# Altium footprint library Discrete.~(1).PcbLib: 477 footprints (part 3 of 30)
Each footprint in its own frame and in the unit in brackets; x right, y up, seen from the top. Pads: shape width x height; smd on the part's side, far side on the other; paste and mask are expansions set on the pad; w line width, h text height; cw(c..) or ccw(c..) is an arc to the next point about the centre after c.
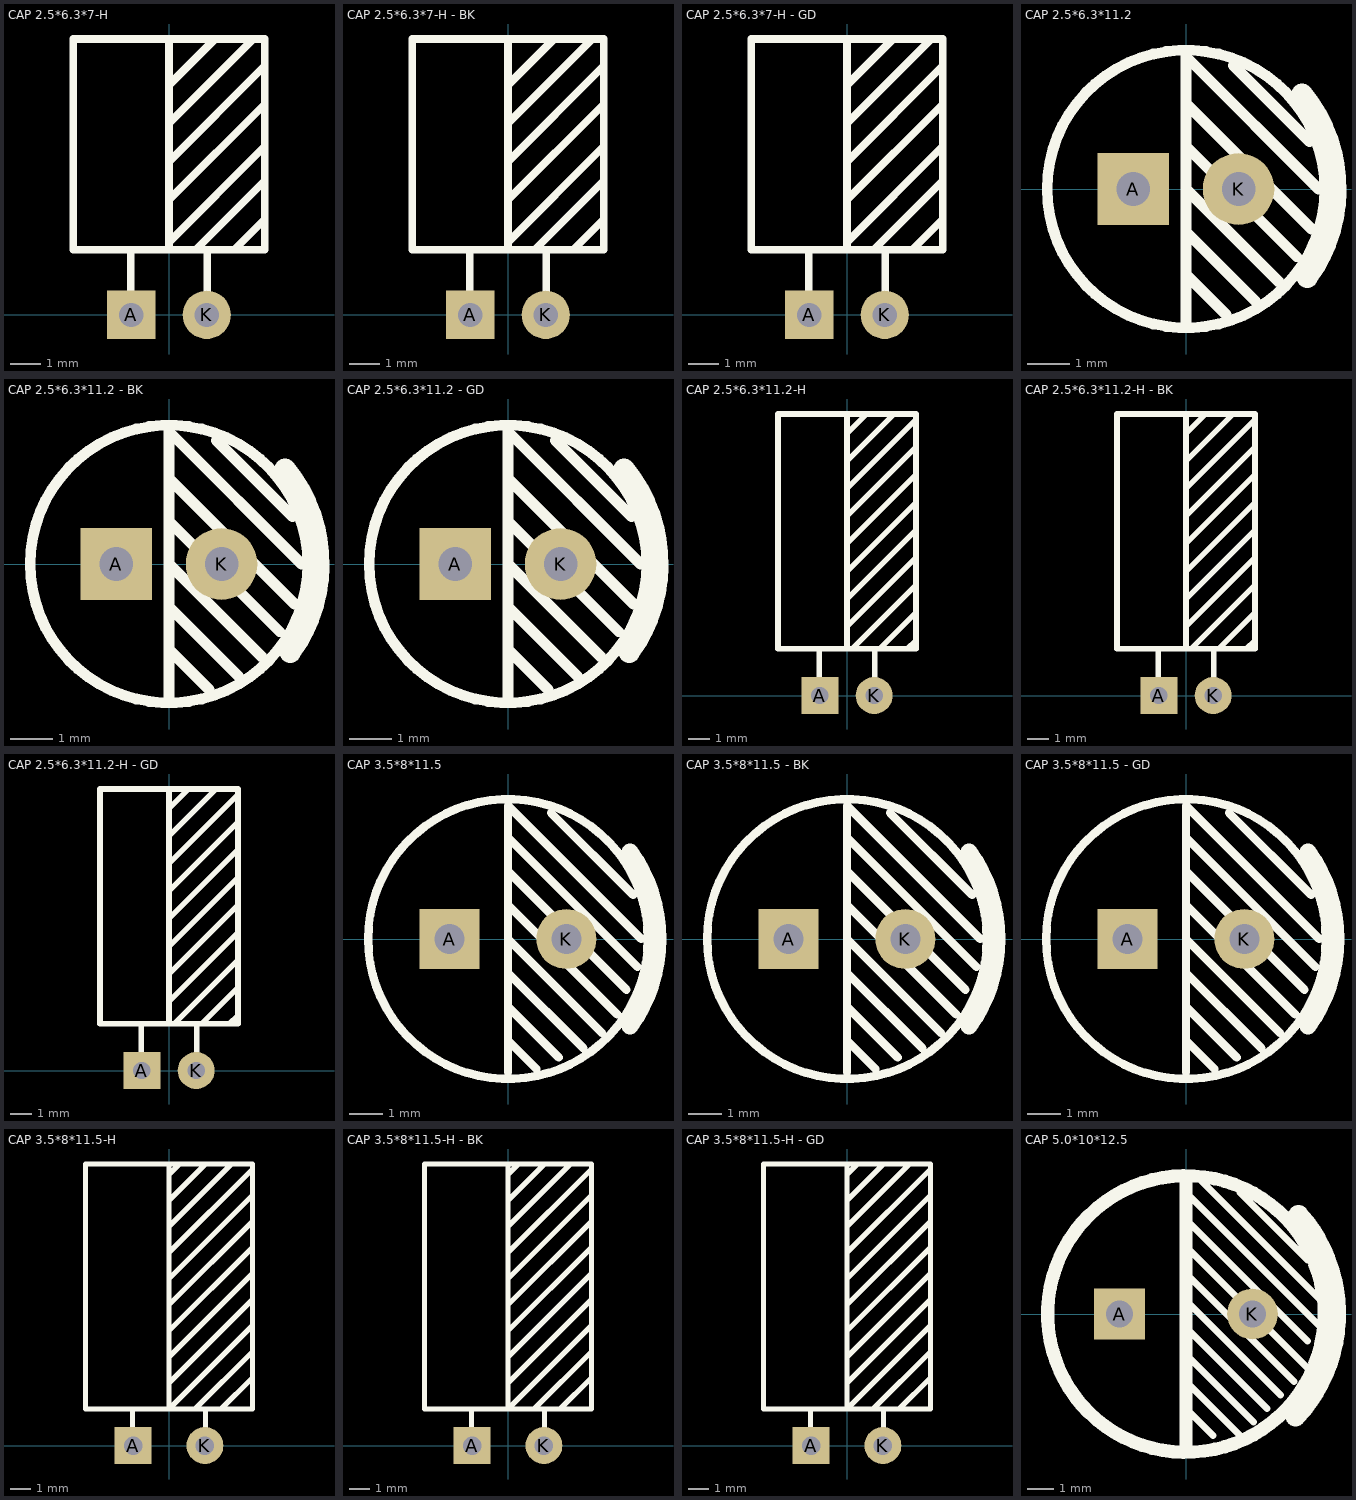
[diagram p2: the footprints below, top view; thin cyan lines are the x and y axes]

## CAP 2.5*6.3*7-H [mm] "脚距2.5mm直径6.3mm高度7mm"
pads (2):
  rect 1.6x1.6 hole 0.8: A(-1.25,0)
  round 1.6 hole 0.8: K(1.25,0)
Top Overlay:
  lines w0.254: -1.27,0.762 -1.27,2.159 ; 0,2.159 0,9.144 ; 0,2.413 3.175,5.588 3.175,5.715 ; 0,3.81 3.175,6.985 ; 0,5.08 3.175,8.255 ; 0,6.35 2.794,9.144 ; 0,7.62 1.524,9.144 ; 0.889,2.159 3.175,4.445 ; 1.27,0.762 1.27,2.159 ; 2.159,2.159 3.175,3.175 ; -3.175,2.159 3.175,2.159 3.175,9.144 -3.175,9.144 -3.175,2.159
3D body "CAP 2.5X6.3X7-H.STEP": height 6.32, standoff -3.48, extent -3.15,-0.3 3.16,8.91

## CAP 2.5*6.3*7-H - BK [mm] "脚距2.5mm直径6.3mm高度7mm"
pads (2):
  rect 1.6x1.6 hole 0.8: A(-1.25,0)
  round 1.6 hole 0.8: K(1.25,0)
Top Overlay:
  lines w0.254: -1.27,0.762 -1.27,2.159 ; 0,2.159 0,9.144 ; 0,2.413 3.175,5.588 3.175,5.715 ; 0,3.81 3.175,6.985 ; 0,5.08 3.175,8.255 ; 0,6.35 2.794,9.144 ; 0,7.62 1.524,9.144 ; 0.889,2.159 3.175,4.445 ; 1.27,0.762 1.27,2.159 ; 2.159,2.159 3.175,3.175 ; -3.175,2.159 3.175,2.159 3.175,9.144 -3.175,9.144 -3.175,2.159
3D body "CAP 2.5X6.3X7-H.STEP": height 6.32, standoff -3.48, extent -3.15,-0.3 3.16,8.91

## CAP 2.5*6.3*7-H - GD [mm] "脚距2.5mm直径6.3mm高度7mm"
pads (2):
  rect 1.6x1.6 hole 0.8: A(-1.25,0)
  round 1.6 hole 0.8: K(1.25,0)
Top Overlay:
  lines w0.254: -1.27,0.762 -1.27,2.159 ; 0,2.159 0,9.144 ; 0,2.413 3.175,5.588 3.175,5.715 ; 0,3.81 3.175,6.985 ; 0,5.08 3.175,8.255 ; 0,6.35 2.794,9.144 ; 0,7.62 1.524,9.144 ; 0.889,2.159 3.175,4.445 ; 1.27,0.762 1.27,2.159 ; 2.159,2.159 3.175,3.175 ; -3.175,2.159 -3.175,9.144 3.175,9.144 3.175,2.159 -3.175,2.159
3D body "CAP 2.5X6.3X7-H.STEP": height 6.32, standoff -3.48, extent -3.15,-0.3 3.16,8.91

## CAP 2.5*6.3*11.2 [mm] "脚距2.5mm直径6.3mm高度11.2mm"
pads (2):
  rect 1.7x1.7 hole 0.8: A(-1.25,0)
  round 1.7 hole 0.8: K(1.25,0)
Top Overlay:
  circle w0.254: c0,0 r3.3
  lines w0.254: 0,-3.15 0,3.15 ; 0,-2.032 0.953,-2.984 ; 0,-1.016 1.638,-2.654 ; 0,0 2.21,-2.21 ; 0,1.016 2.629,-1.613 ; 0,2.032 2.984,-0.953 ; 0,3.048 0.102,3.048 3.15,0 ; 1.13,2.934 2.934,1.13
  lines w0.504: 2.759,2.258 cw(c0,0) 2.883,-2.097
3D body "CAP 2.5X6.3X11.2.STEP": height 11.23, standoff -3.38, extent -3.15,-3.15 3.16,3.15

## CAP 2.5*6.3*11.2 - BK [mm] "脚距2.5mm直径6.3mm高度11.2mm"
pads (2):
  rect 1.7x1.7 hole 0.8: A(-1.25,0)
  round 1.7 hole 0.8: K(1.25,0)
Top Overlay:
  circle w0.254: c0,0 r3.3
  lines w0.254: 0,-3.15 0,3.15 ; 0,-2.032 0.953,-2.984 ; 0,-1.016 1.638,-2.654 ; 0,0 2.21,-2.21 ; 0,1.016 2.629,-1.613 ; 0,2.032 2.984,-0.953 ; 0,3.048 0.102,3.048 3.15,0 ; 1.13,2.934 2.934,1.13
  lines w0.504: 2.759,2.258 cw(c0,0) 2.883,-2.097
3D body "CAP 2.5X6.3X11.2.STEP": height 11.24, standoff -3.37, extent -3.15,-3.15 3.16,3.15

## CAP 2.5*6.3*11.2 - GD [mm] "脚距2.5mm直径6.3mm高度11.2mm"
pads (2):
  rect 1.7x1.7 hole 0.8: A(-1.25,0)
  round 1.7 hole 0.8: K(1.25,0)
Top Overlay:
  circle w0.254: c0,0 r3.3
  lines w0.254: 0,-3.15 0,3.15 ; 0,-2.032 0.953,-2.984 ; 0,-1.016 1.638,-2.654 ; 0,0 2.21,-2.21 ; 0,1.016 2.629,-1.613 ; 0,2.032 2.984,-0.953 ; 0,3.048 0.102,3.048 3.15,0 ; 1.13,2.934 2.934,1.13
  lines w0.504: 2.759,2.258 cw(c0,0) 2.883,-2.097
3D body "CAP 2.5X6.3X11.2.STEP": height 11.24, standoff -3.37, extent -3.15,-3.15 3.16,3.15

## CAP 2.5*6.3*11.2-H [mm] "脚距2.5mm直径6.3mm高度11.2mm"
pads (2):
  rect 1.7x1.7 hole 0.8: A(-1.25,0)
  round 1.7 hole 0.8: K(1.25,0)
Top Overlay:
  lines w0.254: -1.27,0.635 -1.27,2.032 ; 0,2.159 0,12.954 ; 0,3.175 3.175,6.35 ; 0,4.445 3.175,7.62 ; 0,5.715 3.175,8.89 ; 0,6.985 3.175,10.16 ; 0,8.255 3.175,11.43 ; 0,9.525 3.175,12.7 ; 0,10.795 2.159,12.954 ; 0,12.065 0.889,12.954 ; 0.254,2.159 3.175,5.08 3.175,4.953 ; 1.27,0.635 1.27,2.159 ; 1.524,2.159 3.175,3.81 ; 2.794,2.159 3.175,2.54 ; -3.175,2.159 3.175,2.159 3.175,12.954 -3.175,12.954 -3.175,2.159
3D body "CAP 2.5X6.3X11.2-H.STEP": height 6.32, standoff -3.48, extent -3.15,-0.3 3.16,13.11

## CAP 2.5*6.3*11.2-H - BK [mm] "脚距2.5mm直径6.3mm高度11.2mm"
pads (2):
  rect 1.7x1.7 hole 0.8: A(-1.25,0)
  round 1.7 hole 0.8: K(1.25,0)
Top Overlay:
  lines w0.254: -1.27,0.635 -1.27,2.032 ; 0,2.159 0,12.954 ; 0,3.175 3.175,6.35 ; 0,4.445 3.175,7.62 ; 0,5.715 3.175,8.89 ; 0,6.985 3.175,10.16 ; 0,8.255 3.175,11.43 ; 0,9.525 3.175,12.7 ; 0,10.795 2.159,12.954 ; 0,12.065 0.889,12.954 ; 0.254,2.159 3.175,5.08 3.175,4.953 ; 1.27,0.635 1.27,2.159 ; 1.524,2.159 3.175,3.81 ; 2.794,2.159 3.175,2.54 ; -3.175,2.159 3.175,2.159 3.175,12.954 -3.175,12.954 -3.175,2.159
3D body "CAP 2.5X6.3X11.2-H.STEP": height 6.32, standoff -3.48, extent -3.15,-0.3 3.16,13.11

## CAP 2.5*6.3*11.2-H - GD [mm] "脚距2.5mm直径6.3mm高度11.2mm"
pads (2):
  rect 1.7x1.7 hole 0.8: A(-1.25,0)
  round 1.7 hole 0.8: K(1.25,0)
Top Overlay:
  lines w0.254: -1.27,0.635 -1.27,2.032 ; 0,2.159 0,12.954 ; 0,3.175 3.175,6.35 ; 0,4.445 3.175,7.62 ; 0,5.715 3.175,8.89 ; 0,6.985 3.175,10.16 ; 0,8.255 3.175,11.43 ; 0,9.525 3.175,12.7 ; 0,10.795 2.159,12.954 ; 0,12.065 0.889,12.954 ; 0.254,2.159 3.175,5.08 3.175,4.953 ; 1.27,0.635 1.27,2.159 ; 1.524,2.159 3.175,3.81 ; 2.794,2.159 3.175,2.54 ; -3.175,2.159 -3.175,12.954 3.175,12.954 3.175,2.159 -3.175,2.159
3D body "CAP 2.5X6.3X11.2-H.STEP": height 6.32, standoff -3.48, extent -3.15,-0.3 3.16,13.11

## CAP 3.5*8*11.5 [mm] "脚距3.5mm直径8mm高度11.5mm"
pads (2):
  rect 1.8x1.8 hole 0.9: A(-1.75,0)
  round 1.8 hole 0.9: K(1.75,0)
Top Overlay:
  circle w0.254: c0,0 r4.2
  lines w0.254: 0,-4 0,4 4,0 ; 0,-3.048 0.851,-3.899 ; 0,-2.032 1.524,-3.556 ; 0,-1.016 2.261,-3.277 ; 0,0 2.807,-2.807 ; 0,1.016 3.277,-2.261 ; 0,2.032 3.556,-1.524 ; 0,3.048 3.886,-0.838 ; 1.295,3.785 3.759,1.321
  lines w0.504: 3.663,-2.616 ccw(c0,0) 3.663,2.616
3D body "CAP 3.5X8X11.5.STEP": height 11.53, standoff -3.38, extent -4,-4 4.01,4

## CAP 3.5*8*11.5 - BK [mm] "脚距3.5mm直径8mm高度11.5mm"
pads (2):
  rect 1.8x1.8 hole 0.9: A(-1.75,0)
  round 1.8 hole 0.9: K(1.75,0)
Top Overlay:
  circle w0.254: c0,0 r4.2
  lines w0.254: 0,-4 0,4 4,0 ; 0,-3.048 0.851,-3.899 ; 0,-2.032 1.524,-3.556 ; 0,-1.016 2.261,-3.277 ; 0,0 2.807,-2.807 ; 0,1.016 3.277,-2.261 ; 0,2.032 3.556,-1.524 ; 0,3.048 3.886,-0.838 ; 1.295,3.785 3.759,1.321
  lines w0.504: 3.663,-2.616 ccw(c0,0) 3.663,2.616
3D body "CAP 3.5X8X11.5.STEP": height 11.54, standoff -3.37, extent -4,-4 4.01,4

## CAP 3.5*8*11.5 - GD [mm] "脚距3.5mm直径8mm高度11.5mm"
pads (2):
  rect 1.8x1.8 hole 0.9: A(-1.75,0)
  round 1.8 hole 0.9: K(1.75,0)
Top Overlay:
  circle w0.254: c0,0 r4.2
  lines w0.254: 0,-4 0,4 4,0 ; 0,-3.048 0.851,-3.899 ; 0,-2.032 1.524,-3.556 ; 0,-1.016 2.261,-3.277 ; 0,0 2.807,-2.807 ; 0,1.016 3.277,-2.261 ; 0,2.032 3.556,-1.524 ; 0,3.048 3.886,-0.838 ; 1.295,3.785 3.759,1.321
  lines w0.504: 3.663,-2.616 ccw(c0,0) 3.663,2.616
3D body "CAP 3.5X8X11.5.STEP": height 11.54, standoff -3.37, extent -4,-4 4.01,4

## CAP 3.5*8*11.5-H [mm] "脚距3.5mm直径8mm高度11.5mm"
pads (2):
  rect 1.8x1.8 hole 0.9: A(-1.75,0)
  round 1.8 hole 0.9: K(1.75,0)
Top Overlay:
  lines w0.254: -1.778,0.762 -1.778,1.778 ; 0,3.048 4.064,7.112 ; 0,4.318 4.064,8.382 ; 0,5.588 4.064,9.652 ; 0,6.858 4.064,10.922 ; 0,8.128 4.064,12.192 ; 0,9.398 4.064,13.462 ; 0,10.668 3.048,13.716 ; 0,11.938 1.778,13.716 ; 0,13.208 0.508,13.716 ; 0,13.716 0,1.778 4.064,5.842 ; 1.27,1.778 4.064,4.572 ; 1.778,0.762 1.778,1.778 ; 2.54,1.778 4.064,3.302 ; -4.064,1.778 -4.064,13.716 4.064,13.716 4.064,1.778 -4.064,1.778
3D body "CAP 3.5X8X11.5-H.STEP": height 8.03, standoff -2.62, extent -4,-0.3 4.01,13.41

## CAP 3.5*8*11.5-H - BK [mm] "脚距3.5mm直径8mm高度11.5mm"
pads (2):
  rect 1.8x1.8 hole 0.9: A(-1.75,0)
  round 1.8 hole 0.9: K(1.75,0)
Top Overlay:
  lines w0.254: -1.778,0.762 -1.778,1.778 ; 0,3.048 4.064,7.112 ; 0,4.318 4.064,8.382 ; 0,5.588 4.064,9.652 ; 0,6.858 4.064,10.922 ; 0,8.128 4.064,12.192 ; 0,9.398 4.064,13.462 ; 0,10.668 3.048,13.716 ; 0,11.938 1.778,13.716 ; 0,13.208 0.508,13.716 ; 0,13.716 0,1.778 4.064,5.842 ; 1.27,1.778 4.064,4.572 ; 1.778,0.762 1.778,1.778 ; 2.54,1.778 4.064,3.302 ; -4.064,1.778 4.064,1.778 4.064,13.716 -4.064,13.716 -4.064,1.778
3D body "CAP 3.5X8X11.5-H.STEP": height 8.03, standoff -3.48, extent -4,-0.3 4.01,13.41

## CAP 3.5*8*11.5-H - GD [mm] "脚距3.5mm直径8mm高度11.5mm"
pads (2):
  rect 1.8x1.8 hole 0.9: A(-1.75,0)
  round 1.8 hole 0.9: K(1.75,0)
Top Overlay:
  lines w0.254: -1.778,0.762 -1.778,1.778 ; 0,3.048 4.064,7.112 ; 0,4.318 4.064,8.382 ; 0,5.588 4.064,9.652 ; 0,6.858 4.064,10.922 ; 0,8.128 4.064,12.192 ; 0,9.398 4.064,13.462 ; 0,10.668 3.048,13.716 ; 0,11.938 1.778,13.716 ; 0,13.208 0.508,13.716 ; 0,13.716 0,1.778 4.064,5.842 ; 1.27,1.778 4.064,4.572 ; 1.778,0.762 1.778,1.778 ; 2.54,1.778 4.064,3.302 ; -4.064,1.778 4.064,1.778 4.064,13.716 -4.064,13.716 -4.064,1.778
3D body "CAP 3.5X8X11.5-H.STEP": height 8.03, standoff -3.48, extent -4,-0.3 4.01,13.41

## CAP 5.0*10*12.5 [mm] "脚距5mm直径10mm高度12.5mm"
pads (2):
  rect 1.9x1.9 hole 1: A(-2.5,0)
  round 1.9 hole 1: K(2.5,0)
Top Overlay:
  circle w0.5: c0,0 r5.2
  lines w0.254: 0,-3.556 1.016,-4.572 ; 0,-2.54 2.032,-4.572 ; 0,-1.524 2.54,-4.064 ; 0,-1.016 0,-0.508 3.048,-3.556 ; 0,0.508 3.556,-3.048 ; 0,1.524 4.064,-2.54 ; 0,2.54 4.572,-2.032 ; 0,3.556 4.572,-1.016 ; 0,4.572 5.08,-0.508 ; 0.508,5.08 5.08,0.508 ; 2.032,4.572 4.572,2.032
  lines w0.5: 0,-5 0,5
  lines w0.75: 4.114,-3.857 ccw(c0,0) 4.229,3.731
3D body "CAP 5X10X12.5.STEP": height 12.55, standoff -3.36, extent -5.003,-5.006 5.007,4.993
